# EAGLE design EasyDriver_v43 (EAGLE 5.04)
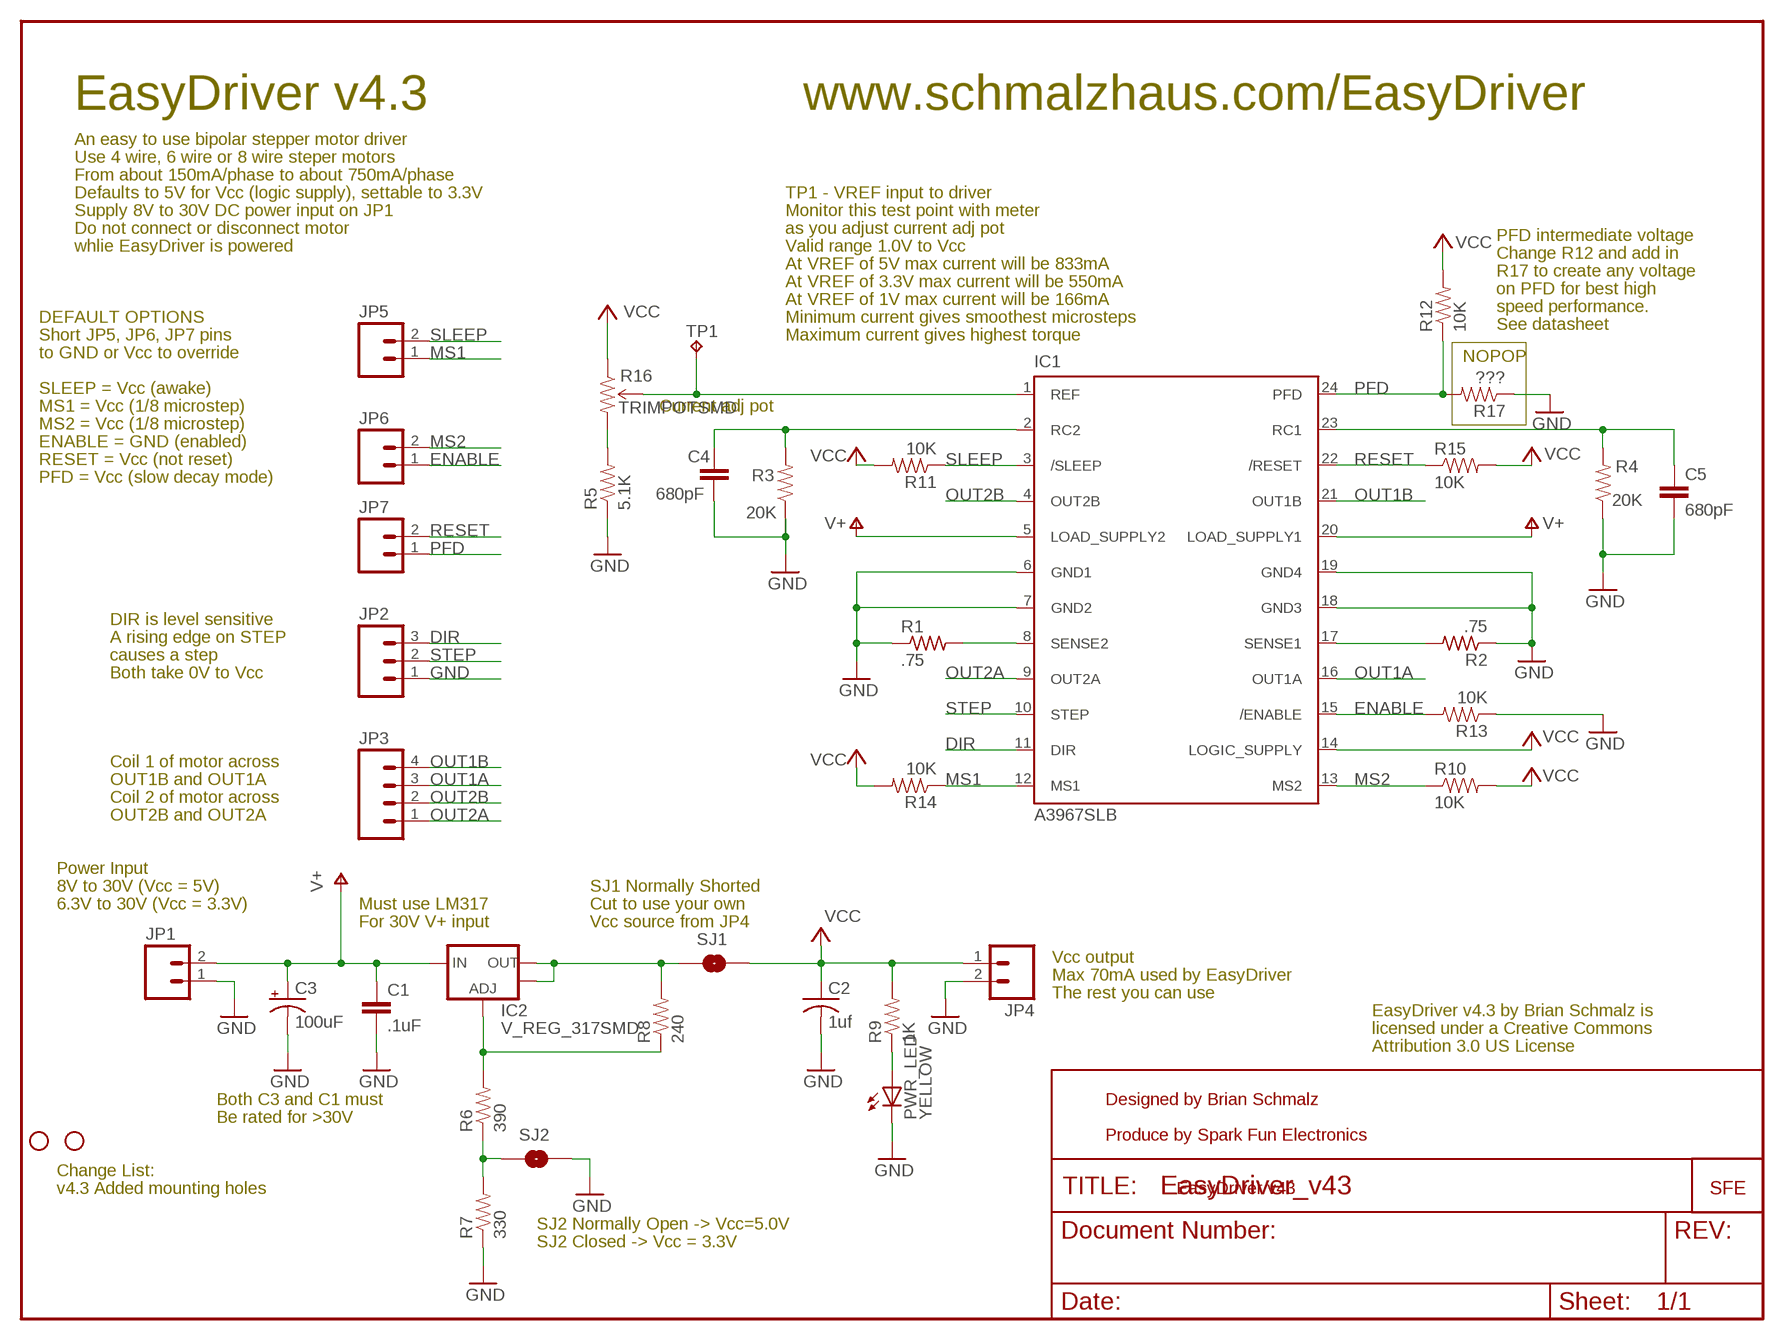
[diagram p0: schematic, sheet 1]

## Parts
C1  .1uF  CAP0603  [0603]
C2  1uf  C-USC0603  [C0603]
C3  100uF  CPOL-USD  [PANASONIC_D]
C4  680pF  CAP0402  [C0402]
C5  680pF  CAP0402  [C0402]
IC1  A3967SLB  [SO24W]
IC2  V_REG_317SMD  [SOT223]
JP1  M021X02_NO_SILK  [1X02_NO_SILK]
JP2  M031X03_NO_SILK  [1X03_NO_SILK]
JP3  M041X04_NO_SILK  [1X04_NO_SILK]
JP4  M021X02_NO_SILK  [1X02_NO_SILK]
JP5  M021X02_NO_SILK  [1X02_NO_SILK]
JP6  M021X02_NO_SILK  [1X02_NO_SILK]
JP7  M021X02_NO_SILK  [1X02_NO_SILK]
JP8  STAND-OFF  [STAND-OFF]
JP9  STAND-OFF  [STAND-OFF]
PWR_LED  YELLOW  LED0603  [LED-0603]
R1  .75  R-US_R0805  [R0805]
R2  .75  R-US_R0805  [R0805]
R3  20K  RESISTOR0402  [C0402]
R4  20K  RESISTOR0402  [C0402]
R5  5.1K  RESISTOR0402  [C0402]
R6  390  RESISTOR0402  [C0402]
R7  330  RESISTOR0402  [C0402]
R8  240  RESISTOR0402  [C0402]
R9  1K  RESISTOR0402  [C0402]
R10  10K  RESISTOR0402  [C0402]
R11  10K  RESISTOR0402  [C0402]
R12  10K  RESISTOR0402  [C0402]
R13  10K  RESISTOR0402  [C0402]
R14  10K  RESISTOR0402  [C0402]
R15  10K  RESISTOR0402  [C0402]
R16  TRIMPOTSMD  [TRIMPOT-3MM]
R17  ???  RESISTOR0402  [C0402]
SJ1  SOLDERJUMPERTRACE  [SJ_2S-TRACE]
SJ2  SOLDERJUMPERNO  [SJ_2S-NO]
TP1  TPPAD1-13  [P1-13]
U$2  LOGO-SFENEW  [SFE-NEW-WEBLOGO]

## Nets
5V_ALT: IC2.2(OUT) IC2.4(OUT) R8.2 SJ1.1
DIR: IC1.11(DIR) JP2.3
ENABLE: IC1.15(/ENABLE) JP6.1 R13.2
GND: C1.2 C2.2 C3.- C4.2 C5.2 IC1.6(GND1) IC1.7(GND2) IC1.18(GND3) IC1.19(GND4) JP1.1 JP2.1 JP4.2 PWR_LED.C R1.1 R2.1 R3.1 R4.1 R5.1 R7.1 R13.1 R17.1 SJ2.2
MS1: IC1.12(MS1) JP5.1 R14.1
MS2: IC1.13(MS2) JP6.2 R10.1
N$1: IC1.8(SENSE2) R1.2
N$2: PWR_LED.A R9.1
N$3: IC1.17(SENSE1) R2.2
N$4: R6.1 R7.2 SJ2.1
N$5: C4.1 IC1.2(RC2) R3.2
N$6: IC2.1(ADJ) R6.2 R8.1
N$7: C5.1 IC1.23(RC1) R4.2
N$11: R5.2 R16.3(CW)
N$12: IC1.1(REF) R16.2(WIPER) TP1.1(TP)
OUT1A: IC1.16(OUT1A) JP3.3
OUT1B: IC1.21(OUT1B) JP3.4
OUT2A: IC1.9(OUT2A) JP3.1
OUT2B: IC1.4(OUT2B) JP3.2
PFD: IC1.24(PFD) JP7.1 R12.1 R17.2
RESET: IC1.22(/RESET) JP7.2 R15.1
SLEEP: IC1.3(/SLEEP) JP5.2 R11.1
STEP: IC1.10(STEP) JP2.2
V+: C1.1 C3.+ IC1.5(LOAD_SUPPLY2) IC1.20(LOAD_SUPPLY1) IC2.3(IN) JP1.2
VCC: C2.1 IC1.14(LOGIC_SUPPLY) JP4.1 R9.2 R10.2 R11.2 R12.2 R14.2 R15.2 R16.1(CCW) SJ1.2

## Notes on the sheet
- EasyDriver v4.3 | www.schmalzhaus.com/EasyDriver
- An easy to use bipolar stepper motor driver
- Use 4 wire, 6 wire or 8 wire steper motors
- From about 150mA/phase to about 750mA/phase
- Defaults to 5V for Vcc (logic supply), settable to 3.3V | TP1 - VREF input to driver
- Supply 8V to 30V DC power input on JP1 | Monitor this test point with meter
- Do not connect or disconnect motor | as you adjust current adj pot
- PFD intermediate voltage
- whlie EasyDriver is powered | Valid range 1.0V to Vcc
- Change R12 and add in
- At VREF of 5V max current will be 833mA
- R17 to create any voltage
- At VREF of 3.3V max current will be 550mA
- on PFD for best high
- At VREF of 1V max current will be 166mA
- speed performance.
- DEFAULT OPTIONS | Minimum current gives smoothest microsteps
- See datasheet
- Short JP5, JP6, JP7 pins | Maximum current gives highest torque
- to GND or Vcc to override | NOPOP
- SLEEP = Vcc (awake)
- MS1 = Vcc (1/8 microstep) | Current adj pot
- MS2 = Vcc (1/8 microstep)
- ENABLE = GND (enabled)
- RESET = Vcc (not reset)
- PFD = Vcc (slow decay mode)
- DIR is level sensitive
- A rising edge on STEP
- causes a step
- Both take 0V to Vcc
- Coil 1 of motor across
- OUT1B and OUT1A
- Coil 2 of motor across
- OUT2B and OUT2A
- Power Input
- 8V to 30V (Vcc = 5V) | SJ1 Normally Shorted
- 6.3V to 30V (Vcc = 3.3V) | Must use LM317 | Cut to use your own
- For 30V V+ input | Vcc source from JP4
- Vcc output
- Max 70mA used by EasyDriver
- The rest you can use
- EasyDriver v4.3 by Brian Schmalz is
- licensed under a Creative Commons
- Attribution 3.0 US License
- Both C3 and C1 must | Designed by Brian Schmalz
- Be rated for >30V
- Produce by Spark Fun Electronics
- Change List:
- v4.3 Added mounting holes | EasyDriver v43
- SJ2 Normally Open -> Vcc=5.0V
- SJ2 Closed -> Vcc = 3.3V

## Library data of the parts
C1 = SparkFun-2-11-09:CAP: Capacitor
C2 = rcl:C-US: CAPACITOR, American symbol
C3 = rcl:CPOL-US: POLARIZED CAPACITOR, American symbol
C4 C5 = SparkFun03_30_09:CAP: Capacitor
IC1 = Allegro:A3967SLB: ANALOG DEVICES
IC2 = SparkFun03_30_09:V_REG_317: Voltage Regulator Standard LM317 adjustable voltage regulator. AOI (Adjust Output Input). Google 'LM317 Calculator' for easy to use app to get the two resistor values needed. 240/720 for 5V output. 240/390 for 3.3V output. Spark Fun Electronics SKU : COM-00527
JP1 JP4-JP7 = SparkFun:M02: Header 2
JP2 = SparkFun:M03: Header 3 Standard 3-pin 0.1" header. Use with straight break away headers (SKU : PRT-00116), right angle break away headers (PRT-00553), swiss pins (PRT-00743), machine pins (PRT-00117), and female headers (PRT-00115). Molex polarized connector foot print use with SKU : PRT-08232 with associated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
JP3 = SparkFun:M04: Header 4 Standard 4-pin 0.1" header. Use with straight break away headers (SKU : PRT-00116), right angle break away headers (PRT-00553), swiss pins (PRT-00743), machine pins (PRT-00117), and female headers (PRT-00115). Molex polarized connector foot print use with SKU : PRT-08231 with associated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
JP8 JP9 = SparkFun-7-28-09:STAND-OFF: Stand Off
PWR_LED = SparkFun03_30_09:LED: LEDs
R1 R2 = rcl:R-US_: RESISTOR, American symbol
R3-R15 R17 = SparkFun03_30_09:RESISTOR: Resistor
R16 = SparkFun:TRIMPOT
SJ1 SJ2 = SparkFun03_30_09:SOLDERJUMPER: Solder Jumper
TP1 = testpad:TP
U$2 = SparkFun:LOGO-SFE: Spark Fun Electronics PCB Logo

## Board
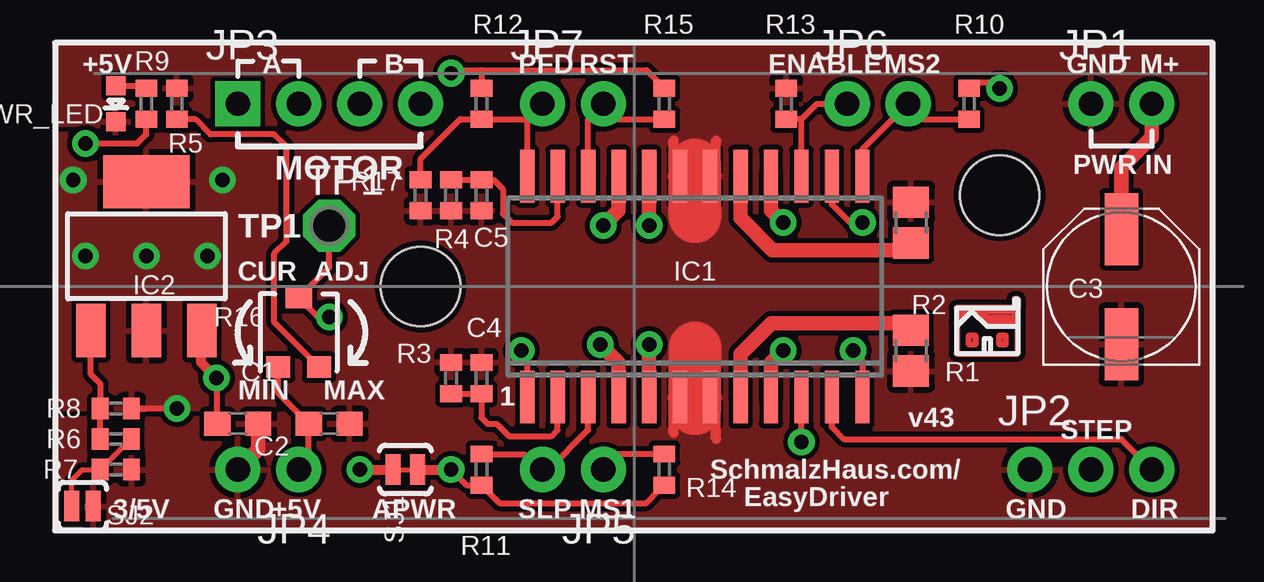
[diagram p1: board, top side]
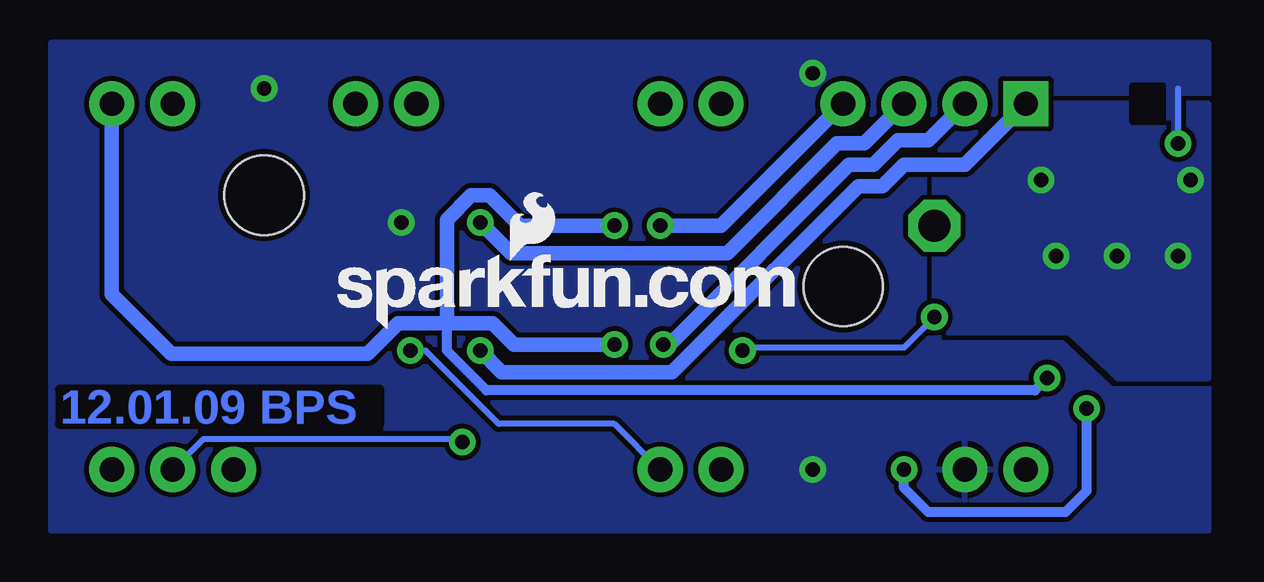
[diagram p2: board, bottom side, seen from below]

No outline drawn. Coordinates in mm, seen from the top.
Copper layers (1*16): Top 0.035mm / dielectric 1.5mm / Bottom 0.035mm
Design rules "SparkFun": minimum track width 8mil, minimum drill 20mil, track to track 8mil, track to pad 8mil, pad to pad 8mil, via to via 8mil, smd to smd 8mil, copper to edge 10mil, drill to drill 8mil, minimum pad ring 12mil, minimum via ring 10mil, stop-mask expansion 4mil, vias tented up to drill 25mil, thermal gap 10mil
bRestrict: area 1.9,17 to 3.2,18.5

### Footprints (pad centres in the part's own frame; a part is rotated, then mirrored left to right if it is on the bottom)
0603 = smd 1.1 x 1: 1 -0.85,0; 2 0.85,0
C0603 = smd 1.1 x 1: 1 -0.85,0; 2 0.85,0
PANASONIC_D = smd 3 x 1.4: + 2.4,0; - -2.4,0
C0402 = smd 0.7 x 0.9: 1 -0.65,0; 2 0.65,0
SO24W = smd 0.6 x 2.2: 1 -6.985,-4.6; 2 -5.715,-4.6; 3 -4.445,-4.6; 4 -3.175,-4.6; 5 -1.905,-4.6; 6 -0.635,-4.6; 7 0.635,-4.6; 8 1.905,-4.6; 9 3.175,-4.6; 10 4.445,-4.6; 11 5.715,-4.6; 12 6.985,-4.6; 13 6.985,4.6; 14 5.715,4.6; 15 4.445,4.6; 16 3.175,4.6; 17 1.905,4.6; 18 0.635,4.6; 19 -0.635,4.6; 20 -1.905,4.6; 21 -3.175,4.6; 22 -4.445,4.6; 23 -5.715,4.6; 24 -6.985,4.6
SOT223 = smd 1.219 x 2.235: 1 -2.311,-3.099; 2 0,-3.099; 3 2.311,-3.099 | smd 3.6 x 2.2: 4 0,3.099
1X02_NO_SILK = drill 1.016 pad 1.88 round: 1 0,0; 2 2.54,0
1X03_NO_SILK = drill 1.016 pad 1.88 round: 1 0,0; 2 2.54,0; 3 5.08,0
1X04_NO_SILK = drill 1.016 pad 1.88 square: 1 0,0 | drill 1.016 pad 1.88 round: 2 2.54,0; 3 5.08,0; 4 7.62,0
STAND-OFF = hole 3.302: 0,0
LED-0603 = smd 0.8 x 0.8: A 0,-0.75; C 0,0.75
R0805 = smd 1.3 x 1.5: 1 -0.85,0; 2 0.85,0
TRIMPOT-3MM = smd 1 x 0.9: 1 -0.85,-1.45; 3 0.85,-1.45 | smd 1.1 x 0.9: 2 0,1.45
SJ_2S-TRACE = smd 0.635 x 1.27: 1 -0.508,0; 2 0.508,0
SJ_2S-NO = smd 0.635 x 1.27: 1 -0.45,0; 2 0.45,0
P1-13 = drill 1.321 pad 2.159 octagon: 1 0,0

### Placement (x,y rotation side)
C1  7.62,4.45 0 top
C2  11.43,4.45 0 top
C3  44.45,10.16 90 top
C4  17.78,6.35 90 top
C5  17.78,13.97 270 top
IC1  26.67,10.16 0 top
IC2  3.81,11.43 0 top
JP1  43.18,17.78 0 top
JP2  40.64,2.54 0 top
JP3  7.62,17.78 0 top
JP4  10.16,2.54 180 top
JP5  22.86,2.54 180 top
JP6  33.02,17.78 0 top
JP7  20.32,17.78 0 top
JP8  39.37,13.97 0 top
JP9  15.24,10.16 0 top
PWR_LED  2.54,17.78 180 top
R1  35.69,7.49 90 top
R2  35.69,12.83 270 top
R3  16.51,6.35 270 top
R4  16.51,13.97 90 top
R5  5.08,17.78 270 top
R6  2.54,3.81 180 top
R7  2.54,2.54 180 top
R8  2.54,5.08 0 top
R9  3.81,17.78 270 top
R10  38.1,17.78 90 top
R11  17.78,2.54 270 top
R12  17.78,17.78 90 top
R13  30.48,17.78 270 top
R14  25.4,2.54 270 top
R15  25.4,17.78 90 top
R16  10.16,8.26 0 top
R17  15.24,13.97 90 top
SJ1  14.61,2.54 0 top
SJ2  1.14,1.02 0 top
TP1  11.43,12.7 0 top
U$1  [SCHMALZHAUS_SMALL]  38.86,7.37 0 top
U$2  36.32,8.38 0 bottom

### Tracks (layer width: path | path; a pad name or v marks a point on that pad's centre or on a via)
5V_ALT  (via drill 0.6)
  Top 0.254: 3.81,5.08 R8.2 v5.08,5.08
  Top 0.406: v12.7,2.54 SJ1.1
  Bottom 0.406: v5.08,5.08 5.08,1.65 5.97,0.76 11.68,0.76 12.7,1.78 v12.7,2.54
  other vias: 1.27,11.43 3.81,11.43 6.35,11.43 6.99,14.61 0.76,14.61
  pour Top (rank 2): 0,5.08 0,16.51 10.16,16.51 10.16,5.08
  pour Bottom (rank 2): 0,17.78 7.62,17.78 10.16,15.24 11.43,15.24 11.43,8.26 5.84,8.26 3.81,6.35 0,6.35
DIR
  Top 0.254: IC1.11 32.38,4.32 32.89,3.81 44.45,3.81 JP2.3
ENABLE
  Top 0.254: IC1.15 31.11,17.14 | 31.11,17.14 31.75,17.78 JP6.1 | R13.2 31.1,17.13 31.11,17.14
GND
  Top 0.406: 27.56,3.81 27.56,7.24 | 27.56,13.21 27.56,16.26 | 25.78,13.21 25.78,16.26 | 25.78,4.06 25.78,6.99
  Top 0.61: C1.2 8.47,3.39 JP4.2
  Top 2.184: 26.67,13.08 26.67,15.24 | 26.67,5.08 26.67,7.62
  pour Top (rank 3): 0,0 0,5.08 0,20.32 48.26,20.32 48.26,0
  pour Bottom (rank 3): 15.24,17.78 17.65,15.24 17.78,15.37 17.65,15.37
MS1  (via drill 0.6)
  Top 0.254: IC1.12 33.66,7.11 v33.27,7.49 | R14.1 23.51,3.19 JP5.1
  Bottom 0.254: v33.27,7.49 32.64,7.49 29.59,4.45 24.77,4.45 JP5.1
MS2
  Top 0.254: IC1.13 33.66,15.88 JP6.2 36.21,17.13 R10.1
N$1
  Top 0.406: 35.31,8.64 35.69,8.64 R1.2
  Top 0.61: IC1.8 28.57,7.34 29.87,8.64 35.31,8.64
N$2
  Top 0.254: PWR_LED.A 3.81,18.53 R9.1
N$3
  Top 0.406: 35.31,11.68 35.69,11.68 R2.2
  Top 0.61: IC1.17 28.57,13.02 29.91,11.68 35.31,11.68
N$4
  Top 0.203: R6.1 3.16,3.81 R7.2 1.14,2.54 0.69,2.09 SJ2.1
N$5
  Top 0.254: R3.2 C4.1 17.78,4.7 18.03,4.45 18.41,4.45 18.92,3.94 20.7,3.94 20.95,4.19 IC1.2
N$6
  Top 0.254: R6.2 R8.1 | 1.91,5.08 1.91,6.1 1.5,6.5 IC2.1
  Top 0.406: 1.27,8.1 1.5,8.1 IC2.1 | R8.1 1.91,5.08
N$7
  Top 0.254: IC1.23 20.95,13.08 20.7,12.83 19.05,12.83 18.67,13.21 18.67,14.22 18.29,14.61 17.8,14.61 C5.1 R4.2
N$11
  Top 0.254: R5.2 5.86,17.13 6.48,16.51 9.14,16.51 9.65,16 9.65,12.05 9.14,11.54 9.14,8.67 R16.3
N$12  (via drill 0.6)
  Top 0.254: IC1.1 19.68,7.24 v19.43,7.49 | TP1.1 11.43,10.97 R16.2 10.97,8.89 v11.43,8.89
  Bottom 0.254: v19.43,7.49 19.3,7.62 12.7,7.62 v11.43,8.89
OUT1A  (via drill 0.6)
  Top 0.406: IC1.16 29.94,14.76
  Top 0.61: 29.84,14.86 IC1.16 29.84,13.34 v30.35,12.83
  Bottom 0.61: v30.35,12.83 29.08,11.56 20.07,11.56 15.49,16.13 14.35,16.13 JP3.3
OUT1B  (via drill 0.6)
  Top 0.61: v22.86,12.7 23.5,13.34 IC1.21
  Bottom 0.61: v22.86,12.7 20.32,12.7 JP3.4
OUT2A  (via drill 0.6)
  Top 0.406: IC1.9 29.75,5.56
  Top 0.61: 29.84,5.46 IC1.9 29.84,6.99 v30.35,7.49
  Bottom 0.406: 21.46,7.49 21.47,7.49
  Bottom 0.61: 21.46,7.49 14.61,14.35 13.59,14.35 12.7,15.24 10.16,15.24 JP3.1 | v30.35,7.49 29.46,6.6 22.36,6.6 21.47,7.49
OUT2B  (via drill 0.6)
  Top 0.61: v22.73,7.75 23.5,6.99 IC1.4
  Bottom 0.61: v22.73,7.75 22.35,7.87 14.99,15.24 13.97,15.24 12.95,16.26 11.68,16.26 JP3.2
PFD
  Top 0.254: 19.68,14.73 IC1.24 19.68,17.14 19.67,17.13 | 17.8,17.13 19.67,17.13 | R17.2 15.24,15.49 16.89,17.14 17.77,17.14 R12.1 | 19.67,17.13 JP7.1
  Top 0.406: R12.1 17.8,17.13
RESET
  Top 0.254: IC1.22 22.23,17.14 JP7.2 23.51,17.13 R15.1
SLEEP
  Top 0.254: 17.8,3.17 19.56,3.17 20.19,2.54 JP5.2 20.57,2.54 22.23,4.19 IC1.3
  Top 0.305: IC1.3 22.23,5.59
  Top 0.406: R11.1 17.8,3.17
STEP  (via drill 0.6)
  Top 0.254: v31.11,3.68 IC1.10
  Bottom 0.254: v31.11,3.68 31.24,3.81 41.91,3.81 JP2.2
V+  (via drill 0.6)
  Top 0.254: C1.1 6.77,6.31 v6.73,6.35
  Top 0.406: v6.73,6.35 6.1,6.99 6.1,8.31 6.12,8.31 IC2.3
  Top 0.61: v24.77,12.7 IC1.20 | v24.77,7.75 IC1.5 | C3.+ 44.45,15.11 45.72,16.38 JP1.2
  Bottom 0.406: 31.75,8.64 31.75,7.49 30.1,5.84 7.24,5.84 v6.73,6.35
  Bottom 0.61: v24.77,7.75 28.96,7.75 29.84,8.64 31.75,8.64 | 31.75,8.64 33.78,8.64 35.05,7.37 43.25,7.37 45.72,9.83 JP1.2 | v24.77,12.7 28.7,12.7 29.97,13.97 30.73,13.97 31.75,12.95 31.75,8.64
VCC  (via drill 0.6)
  Top 0.254: IC1.14 32.38,13.59 33.15,12.83 v33.66,12.83 | 39.35,18.43 v39.37,18.41 39.12,18.67 38.1,18.67 R10.2 | R14.2 25.18,1.69 24.64,1.14 18.53,1.14 R11.2 17.16,1.89 v16.51,2.54 | R15.2 24.65,19.18 17.78,19.18 | 17.78,19.18 16.64,19.18 v16.51,19.05 | 17.78,19.18 R12.2 | R9.2 3.81,16.51 3.43,16.13 v1.27,16.13 | R16.1 9.31,5.71 C2.1 10.58,2.96 JP4.1
  Top 0.406: R15.2 25.41,18.43 | SJ1.2 v16.51,2.54
  Bottom 0.254: v1.27,16.13 1.27,18.41
  pour Bottom (rank 4): 0,0 0,20.32 48.26,20.32 48.26,0

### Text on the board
Bottom: 12.01.09 BPS
tPlace: +5V | A | B | PFD | RST | ENABLE | MS2 | GND | M+ | MOTOR | PWR IN | TP1 | CUR | ADJ | MIN | MAX | 1 | v43 | STEP | SchmalzHaus.com/ | 3/5V | GND | +5V | APWR | SLP | MS1 | EasyDriver | GND | DIR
